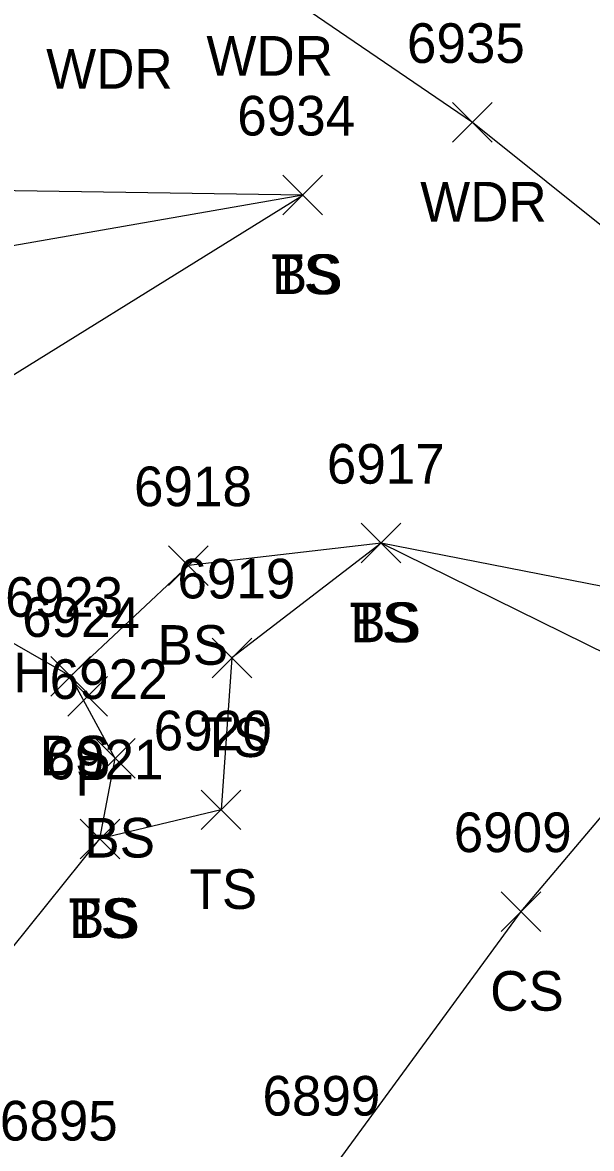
# Model space of a CAD drawing. Extents: x 1439173 to 1457902, y 641926 to 659889.
# Drawn here: x 1448889.8 to 1448918.5, y 643813.5 to 643870.3 of the extents above; entities that cross this region are included whole.
import ezdxf

# ---------------------------------------------------------------- set-up
doc = ezdxf.new("R2010")
doc.units = 0
for name, color, linetype in [('D_A', 7, 'Continuous'), ('D_I', 7, 'Continuous'), ('D_TIC', 7, 'Continuous'), ('L_A', 7, 'Continuous'), ('L_C', 7, 'Continuous'), ('L_I', 7, 'Continuous'), ('L_TIC', 7, 'Continuous'), ('LAWA', 7, 'Continuous'), ('LELB', 7, 'Continuous')]:
    doc.layers.add(name, color=color, linetype=linetype)

msp = doc.modelspace()

# ---------------------------------------------------------------- linework, layer by layer
at = {"layer": 'D_TIC'}
for points in [[(1448892.058, 643835.35), (1448894.058, 643837.35)], [(1448894.058, 643835.35), (1448892.058, 643837.35)]]:
    msp.add_lwpolyline(points, dxfattribs=at)
at = {"layer": 'L_TIC'}
for points in [[(1448911.473, 643864.306), (1448913.473, 643866.306)], [(1448913.473, 643864.306), (1448911.473, 643866.306)], [(1448902.911, 643860.643), (1448904.911, 643862.643)], [(1448904.911, 643860.643), (1448902.911, 643862.643)], [(1448902.911, 643860.643), (1448904.911, 643862.643)], [(1448904.911, 643860.643), (1448902.911, 643862.643)], [(1448906.865, 643843.082), (1448908.865, 643845.082)], [(1448908.865, 643843.082), (1448906.865, 643845.082)], [(1448906.865, 643843.082), (1448908.865, 643845.082)], [(1448908.865, 643843.082), (1448906.865, 643845.082)], [(1448897.138, 643841.945), (1448899.138, 643843.945)], [(1448899.138, 643841.945), (1448897.138, 643843.945)], [(1448899.336, 643837.292), (1448901.336, 643839.292)], [(1448901.336, 643837.292), (1448899.336, 643839.292)], [(1448891.201, 643836.365), (1448893.201, 643838.365)], [(1448893.201, 643836.365), (1448891.201, 643838.365)], [(1448891.201, 643836.365), (1448893.201, 643838.365)], [(1448893.201, 643836.365), (1448891.201, 643838.365)], [(1448893.449, 643832.22), (1448895.449, 643834.22)], [(1448895.449, 643832.22), (1448893.449, 643834.22)], [(1448898.787, 643829.628), (1448900.787, 643831.628)], [(1448900.787, 643829.628), (1448898.787, 643831.628)], [(1448892.676, 643828.162), (1448894.676, 643830.162)], [(1448894.676, 643828.162), (1448892.676, 643830.162)], [(1448892.676, 643828.162), (1448894.676, 643830.162)], [(1448894.676, 643828.162), (1448892.676, 643830.162)], [(1448913.924, 643824.494), (1448915.924, 643826.494)], [(1448915.924, 643824.494), (1448913.924, 643826.494)]]:
    msp.add_lwpolyline(points, dxfattribs=at)
at = {"layer": 'LAWA'}
msp.add_lwpolyline([(1448935.189, 643849.955), (1448930.895, 643850.557), (1448912.473, 643865.306), (1448901.687, 643872.662), (1448893.603, 643872.007), (1448887.665, 643878.897), (1448880.145, 643880.342), (1448877.428, 643885.559), (1448873.118, 643888.685), (1448872.177, 643891.063), (1448868.851, 643895.5), (1448865.458, 643900.525), (1448866.992, 643904.367), (1448875.78, 643920.399), (1448875.617, 643935.584), (1448881.787, 643957.412), (1448868.1, 643977.702), (1448859.214, 644002.854), (1448858.885, 644027.761), (1448856.912, 644066.774)], dxfattribs=at)
at = {"layer": 'LELB'}
for points in [[(1448905.092, 643733.215), (1448906.974, 643730.807), (1448908.131, 643731.204), (1448906.193, 643734.411), (1448895.749, 643755.884), (1448892.962, 643769.945), (1448887.765, 643800.921), (1448885.641, 643819.169), (1448893.676, 643829.162), (1448894.449, 643833.22), (1448892.201, 643837.365), (1448884.102, 643842.019), (1448882.434, 643835.273), (1448877.693, 643835.652), (1448876.059, 643854.096), (1448884.608, 643849.666), (1448903.911, 643861.643), (1448886.483, 643858.598), (1448878.127, 643861.993), (1448876.453, 643873.193), (1448877.428, 643885.559), (1448880.281, 643887.778)], [(1448903.911, 643861.643), (1448884.905, 643861.926), (1448881.631, 643864.904), (1448879.359, 643874.185), (1448880.145, 643880.342)], [(1448934.394, 643844.174), (1448926.249, 643840.484), (1448907.865, 643844.082), (1448898.138, 643842.945), (1448892.201, 643837.365)], [(1449002.891, 643843.223), (1448966.837, 643835.605), (1448936.021, 643837.194), (1448923.94, 643836.16), (1448907.865, 643844.082), (1448900.336, 643838.292), (1448899.787, 643830.628), (1448893.676, 643829.162)], [(1448895.29, 643770.696), (1448906.898, 643793.869), (1448905.192, 643812.204), (1448914.924, 643825.494), (1448923.94, 643836.16)]]:
    msp.add_lwpolyline(points, dxfattribs=at)

# ---------------------------------------------------------------- texts
at = {"layer": 'D_A'}
msp.add_text('P', height=2, dxfattribs=at).set_placement((1448892.436, 643831.35))
at = {"layer": 'D_I'}
msp.add_text('6924', height=2, dxfattribs=at).set_placement((1448889.751, 643839.35))
at = {"layer": 'L_A'}
for s, p in [('WDR', (1448899.049, 643867.662)), ('WDR', (1448890.965, 643867.007)), ('WDR', (1448909.835, 643860.306)), ('TS', (1448902.321, 643856.643)), ('BS', (1448902.352, 643856.643)), ('TS', (1448906.274, 643839.082)), ('BS', (1448906.306, 643839.082)), ('BS', (1448896.579, 643837.945)), ('TS', (1448898.745, 643833.292)), ('BS', (1448890.642, 643832.365)), ('BS', (1448890.642, 643832.365)), ('BS', (1448892.89, 643828.22)), ('TS', (1448898.197, 643825.628)), ('TS', (1448892.085, 643824.162)), ('BS', (1448892.117, 643824.162)), ('CS', (1448913.365, 643820.494))]:
    msp.add_text(s, height=2, dxfattribs=at).set_placement(p)
at = {"layer": 'L_C'}
msp.add_text('S.ASH', height=2, dxfattribs=at).set_placement((1448883.205, 643836.556))
at = {"layer": 'L_I'}
for s, p in [('6935', (1448909.166, 643868.306)), ('6934', (1448900.604, 643864.643)), ('6934', (1448900.604, 643864.643)), ('6917', (1448905.125, 643847.082)), ('6917', (1448905.125, 643847.082)), ('6918', (1448895.398, 643845.945)), ('6919', (1448897.588, 643841.292)), ('6923', (1448888.894, 643840.365)), ('6923', (1448888.894, 643840.365)), ('6922', (1448891.142, 643836.22)), ('6920', (1448896.393, 643833.628)), ('6921', (1448890.936, 643832.162)), ('6921', (1448890.936, 643832.162)), ('6909', (1448911.53, 643828.494)), ('6899', (1448901.877, 643815.204)), ('6899', (1448901.877, 643815.204)), ('6895', (1448888.627, 643813.946))]:
    msp.add_text(s, height=2, dxfattribs=at).set_placement(p)

doc.saveas('drawing.dxf')
